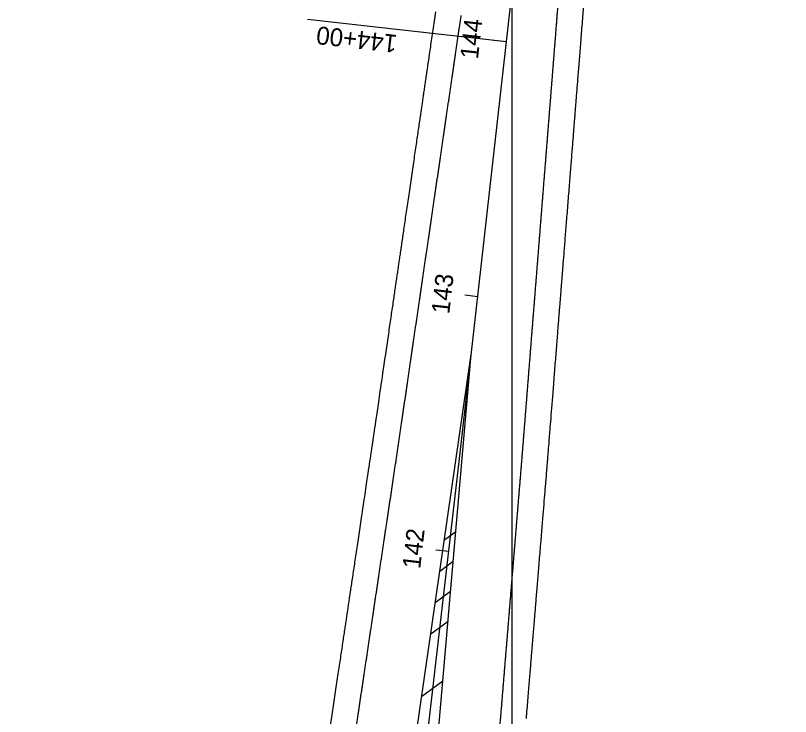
# Model space of a CAD drawing. Extents: x 2318076 to 2324211, y 613525 to 630327.
# Drawn here: x 2320476.3 to 2320778.2, y 628702.1 to 628975.4 of the extents above; entities that cross this region are included whole.
import ezdxf

# ---------------------------------------------------------------- set-up
doc = ezdxf.new("R2010")
doc.units = 0
for name, color, linetype in [('GE_P_CL_50', 7, 'Continuous'), ('PM_P_CL_Double_Solid', 7, 'Continuous'), ('PM_P_Transverse_Line', 7, 'Continuous'), ('PV_P_EOP', 7, 'Continuous'), ('PV_P_Shoulder', 7, 'Continuous'), ('SC_Scratch3', 7, 'Continuous')]:
    doc.layers.add(name, color=color, linetype=linetype)

msp = doc.modelspace()

# ---------------------------------------------------------------- linework, layer by layer
at = {"layer": 'GE_P_CL_50'}
for p, q in [((2320667.58, 628965.13), (2320590.07, 628973.86)), ((2320667.58, 628965.13), (2320662.61, 628965.69)), ((2320656.38, 628865.76), (2320651.41, 628866.32)), ((2320645.08, 628766.4), (2320640.11, 628766.97))]:
    msp.add_line(p, q, dxfattribs=at)
msp.add_lwpolyline([(2320476.3, 627307.7), (2320485.22, 627375.57), (2320502.11, 627520.92), (2320519.22, 627676.47), (2320531.82, 627783.89), (2320546.8, 627927.12), (2320554.45, 627991.34), (2320572.51, 628138.41), (2320649.52, 628804.84), (2320678.77, 629064.5), (2320690.76, 629163.78), (2320713.75, 629362.45), (2320725.26, 629461.78), (2320736.97, 629561.09), (2320748.4, 629660.43), (2320759.09, 629759.86), (2320769.62, 629859.3), (2320777.51, 629931.12), (2320778.25, 629937.84)], dxfattribs=at)
at = {"layer": 'PM_P_CL_Double_Solid'}
for p in [(2320623.21, 628631.42), (2320635.3, 628629.45)]:
    msp.add_line(p, (2320653.84, 628843.21), dxfattribs=at)
at = {"layer": 'PM_P_Transverse_Line'}
for p, q in [((2320647.85, 628774.12), (2320643.47, 628770.85)), ((2320646.84, 628762.47), (2320641.6, 628758.56)), ((2320645.83, 628750.83), (2320639.83, 628746.35)), ((2320644.82, 628739.18), (2320638.07, 628734.13)), ((2320642.8, 628715.89), (2320634.53, 628709.71))]:
    msp.add_line(p, q, dxfattribs=at)
at = {"layer": 'PV_P_EOP'}
for points in [[(2320687.04, 628971.2), (2320687.12, 628972.11), (2320687.19, 628973.02), (2320687.26, 628973.93), (2320687.33, 628974.84), (2320687.4, 628975.75), (2320687.48, 628976.66), (2320687.55, 628977.57), (2320687.62, 628978.48), (2320687.69, 628979.38), (2320687.77, 628980.29), (2320687.84, 628981.2), (2320687.91, 628982.11), (2320687.98, 628983.02), (2320688.05, 628983.93), (2320688.13, 628984.84), (2320688.2, 628985.75), (2320688.27, 628986.66), (2320688.34, 628987.57), (2320688.42, 628988.47), (2320688.49, 628989.38), (2320688.56, 628990.29), (2320688.63, 628991.2), (2320688.7, 628992.11), (2320688.78, 628993.02), (2320688.85, 628993.93), (2320688.92, 628994.84), (2320688.99, 628995.75), (2320689.07, 628996.66), (2320689.14, 628997.57), (2320689.21, 628998.47), (2320689.28, 628999.38), (2320689.35, 629000.29), (2320689.43, 629001.2), (2320689.5, 629002.11), (2320689.57, 629003.02), (2320689.64, 629003.93), (2320689.71, 629004.84), (2320689.79, 629005.75), (2320689.86, 629006.66), (2320689.93, 629007.56), (2320690, 629008.47), (2320690.08, 629009.38), (2320690.15, 629010.29), (2320690.22, 629011.2), (2320690.29, 629012.11), (2320690.36, 629013.02), (2320690.44, 629013.93), (2320690.51, 629014.84), (2320690.58, 629015.75), (2320690.65, 629016.65), (2320690.73, 629017.56), (2320690.8, 629018.47), (2320690.87, 629019.38), (2320690.94, 629020.29), (2320691.01, 629021.2), (2320691.09, 629022.11), (2320691.16, 629023.02), (2320691.23, 629023.93), (2320691.3, 629024.84), (2320691.37, 629025.75), (2320691.45, 629026.65), (2320691.52, 629027.56), (2320691.59, 629028.47), (2320691.66, 629029.38), (2320691.74, 629030.29), (2320691.81, 629031.2), (2320691.88, 629032.11), (2320691.95, 629033.02), (2320692.02, 629033.93), (2320692.1, 629034.84), (2320692.17, 629035.74), (2320692.24, 629036.65), (2320692.31, 629037.56), (2320692.39, 629038.47)], [(2320640.19, 628908.61), (2320640.32, 628909.51), (2320640.45, 628910.41), (2320640.58, 628911.32), (2320640.72, 628912.22), (2320640.85, 628913.12), (2320640.98, 628914.02), (2320641.11, 628914.93), (2320641.24, 628915.83), (2320641.37, 628916.73), (2320641.51, 628917.63), (2320641.64, 628918.54), (2320641.77, 628919.44), (2320641.9, 628920.34), (2320642.03, 628921.24), (2320642.17, 628922.14), (2320642.3, 628923.05), (2320642.43, 628923.95), (2320642.56, 628924.85), (2320642.69, 628925.75), (2320642.82, 628926.66), (2320642.96, 628927.56), (2320643.09, 628928.46), (2320643.22, 628929.36), (2320643.35, 628930.27), (2320643.48, 628931.17), (2320643.62, 628932.07), (2320643.75, 628932.97), (2320643.88, 628933.87), (2320644.01, 628934.78), (2320644.14, 628935.68), (2320644.28, 628936.58), (2320644.41, 628937.48), (2320644.54, 628938.39), (2320644.67, 628939.29), (2320644.8, 628940.19), (2320644.93, 628941.09), (2320645.07, 628942), (2320645.2, 628942.9), (2320645.33, 628943.8), (2320645.46, 628944.7), (2320645.59, 628945.6), (2320645.73, 628946.51), (2320645.86, 628947.41), (2320645.99, 628948.31), (2320646.12, 628949.21), (2320646.25, 628950.12), (2320646.39, 628951.02), (2320646.52, 628951.92), (2320646.65, 628952.82), (2320646.78, 628953.73), (2320646.91, 628954.63), (2320647.04, 628955.53), (2320647.18, 628956.43), (2320647.31, 628957.34), (2320647.44, 628958.24), (2320647.57, 628959.14), (2320647.7, 628960.04), (2320647.84, 628960.94), (2320647.97, 628961.85), (2320648.1, 628962.75), (2320648.23, 628963.65), (2320648.36, 628964.55), (2320648.49, 628965.46), (2320648.63, 628966.36), (2320648.76, 628967.26), (2320648.89, 628968.16), (2320649.02, 628969.07), (2320649.15, 628969.97), (2320649.29, 628970.87), (2320649.42, 628971.77), (2320649.55, 628972.67), (2320649.68, 628973.58), (2320649.81, 628974.48), (2320649.95, 628975.38)], [(2320681.7, 628903.93), (2320681.78, 628904.84), (2320681.85, 628905.75), (2320681.92, 628906.66), (2320681.99, 628907.57), (2320682.06, 628908.48), (2320682.14, 628909.39), (2320682.21, 628910.3), (2320682.28, 628911.21), (2320682.35, 628912.11), (2320682.42, 628913.02), (2320682.5, 628913.93), (2320682.57, 628914.84), (2320682.64, 628915.75), (2320682.71, 628916.66), (2320682.79, 628917.57), (2320682.86, 628918.48), (2320682.93, 628919.39), (2320683, 628920.3), (2320683.07, 628921.21), (2320683.15, 628922.11), (2320683.22, 628923.02), (2320683.29, 628923.93), (2320683.36, 628924.84), (2320683.44, 628925.75), (2320683.51, 628926.66), (2320683.58, 628927.57), (2320683.65, 628928.48), (2320683.72, 628929.39), (2320683.8, 628930.3), (2320683.87, 628931.2), (2320683.94, 628932.11), (2320684.01, 628933.02), (2320684.08, 628933.93), (2320684.16, 628934.84), (2320684.23, 628935.75), (2320684.3, 628936.66), (2320684.37, 628937.57), (2320684.45, 628938.48), (2320684.52, 628939.39), (2320684.59, 628940.3), (2320684.66, 628941.2), (2320684.73, 628942.11), (2320684.81, 628943.02), (2320684.88, 628943.93), (2320684.95, 628944.84), (2320685.02, 628945.75), (2320685.1, 628946.66), (2320685.17, 628947.57), (2320685.24, 628948.48), (2320685.31, 628949.39), (2320685.38, 628950.29), (2320685.46, 628951.2), (2320685.53, 628952.11), (2320685.6, 628953.02), (2320685.67, 628953.93), (2320685.74, 628954.84), (2320685.82, 628955.75), (2320685.89, 628956.66), (2320685.96, 628957.57), (2320686.03, 628958.48), (2320686.11, 628959.39), (2320686.18, 628960.29), (2320686.25, 628961.2), (2320686.32, 628962.11), (2320686.39, 628963.02), (2320686.47, 628963.93), (2320686.54, 628964.84), (2320686.61, 628965.75), (2320686.68, 628966.66), (2320686.76, 628967.57), (2320686.83, 628968.48), (2320686.9, 628969.38), (2320686.97, 628970.29), (2320687.04, 628971.2)], [(2320630.43, 628841.84), (2320630.56, 628842.74), (2320630.69, 628843.64), (2320630.83, 628844.54), (2320630.96, 628845.45), (2320631.09, 628846.35), (2320631.22, 628847.25), (2320631.35, 628848.15), (2320631.49, 628849.06), (2320631.62, 628849.96), (2320631.75, 628850.86), (2320631.88, 628851.76), (2320632.01, 628852.67), (2320632.14, 628853.57), (2320632.28, 628854.47), (2320632.41, 628855.37), (2320632.54, 628856.28), (2320632.67, 628857.18), (2320632.8, 628858.08), (2320632.94, 628858.98), (2320633.07, 628859.88), (2320633.2, 628860.79), (2320633.33, 628861.69), (2320633.46, 628862.59), (2320633.59, 628863.49), (2320633.73, 628864.4), (2320633.86, 628865.3), (2320633.99, 628866.2), (2320634.12, 628867.1), (2320634.25, 628868.01), (2320634.39, 628868.91), (2320634.52, 628869.81), (2320634.65, 628870.71), (2320634.78, 628871.61), (2320634.91, 628872.52), (2320635.05, 628873.42), (2320635.18, 628874.32), (2320635.31, 628875.22), (2320635.44, 628876.13), (2320635.57, 628877.03), (2320635.7, 628877.93), (2320635.84, 628878.83), (2320635.97, 628879.74), (2320636.1, 628880.64), (2320636.23, 628881.54), (2320636.36, 628882.44), (2320636.5, 628883.34), (2320636.63, 628884.25), (2320636.76, 628885.15), (2320636.89, 628886.05), (2320637.02, 628886.95), (2320637.16, 628887.86), (2320637.29, 628888.76), (2320637.42, 628889.66), (2320637.55, 628890.56), (2320637.68, 628891.47), (2320637.81, 628892.37), (2320637.95, 628893.27), (2320638.08, 628894.17), (2320638.21, 628895.07), (2320638.34, 628895.98), (2320638.47, 628896.88), (2320638.61, 628897.78), (2320638.74, 628898.68), (2320638.87, 628899.59), (2320639, 628900.49), (2320639.13, 628901.39), (2320639.26, 628902.29), (2320639.4, 628903.2), (2320639.53, 628904.1), (2320639.66, 628905), (2320639.79, 628905.9), (2320639.92, 628906.81), (2320640.06, 628907.71), (2320640.19, 628908.61)], [(2320676.36, 628836.66), (2320676.43, 628837.57), (2320676.51, 628838.48), (2320676.58, 628839.39), (2320676.65, 628840.3), (2320676.72, 628841.21), (2320676.8, 628842.12), (2320676.87, 628843.03), (2320676.94, 628843.94), (2320677.01, 628844.85), (2320677.08, 628845.75), (2320677.16, 628846.66), (2320677.23, 628847.57), (2320677.3, 628848.48), (2320677.37, 628849.39), (2320677.44, 628850.3), (2320677.52, 628851.21), (2320677.59, 628852.12), (2320677.66, 628853.03), (2320677.73, 628853.94), (2320677.81, 628854.84), (2320677.88, 628855.75), (2320677.95, 628856.66), (2320678.02, 628857.57), (2320678.09, 628858.48), (2320678.17, 628859.39), (2320678.24, 628860.3), (2320678.31, 628861.21), (2320678.38, 628862.12), (2320678.46, 628863.03), (2320678.53, 628863.94), (2320678.6, 628864.84), (2320678.67, 628865.75), (2320678.74, 628866.66), (2320678.82, 628867.57), (2320678.89, 628868.48), (2320678.96, 628869.39), (2320679.03, 628870.3), (2320679.1, 628871.21), (2320679.18, 628872.12), (2320679.25, 628873.03), (2320679.32, 628873.93), (2320679.39, 628874.84), (2320679.47, 628875.75), (2320679.54, 628876.66), (2320679.61, 628877.57), (2320679.68, 628878.48), (2320679.75, 628879.39), (2320679.83, 628880.3), (2320679.9, 628881.21), (2320679.97, 628882.12), (2320680.04, 628883.03), (2320680.12, 628883.93), (2320680.19, 628884.84), (2320680.26, 628885.75), (2320680.33, 628886.66), (2320680.4, 628887.57), (2320680.48, 628888.48), (2320680.55, 628889.39), (2320680.62, 628890.3), (2320680.69, 628891.21), (2320680.76, 628892.12), (2320680.84, 628893.02), (2320680.91, 628893.93), (2320680.98, 628894.84), (2320681.05, 628895.75), (2320681.13, 628896.66), (2320681.2, 628897.57), (2320681.27, 628898.48), (2320681.34, 628899.39), (2320681.41, 628900.3), (2320681.49, 628901.21), (2320681.56, 628902.12), (2320681.63, 628903.02), (2320681.7, 628903.93)], [(2320620.59, 628775.15), (2320620.72, 628776.05), (2320620.86, 628776.95), (2320620.99, 628777.85), (2320621.12, 628778.76), (2320621.26, 628779.66), (2320621.39, 628780.56), (2320621.53, 628781.46), (2320621.66, 628782.36), (2320621.8, 628783.27), (2320621.93, 628784.17), (2320622.07, 628785.07), (2320622.2, 628785.97), (2320622.34, 628786.87), (2320622.47, 628787.78), (2320622.6, 628788.68), (2320622.74, 628789.58), (2320622.87, 628790.48), (2320623.01, 628791.38), (2320623.14, 628792.29), (2320623.28, 628793.19), (2320623.41, 628794.09), (2320623.55, 628794.99), (2320623.68, 628795.89), (2320623.81, 628796.8), (2320623.95, 628797.7), (2320624.08, 628798.6), (2320624.22, 628799.5), (2320624.35, 628800.4), (2320624.49, 628801.31), (2320624.62, 628802.21), (2320624.76, 628803.11), (2320624.89, 628804.01), (2320625.02, 628804.91), (2320625.16, 628805.82), (2320625.29, 628806.72), (2320625.43, 628807.62), (2320625.55, 628808.45), (2320625.68, 628809.35), (2320625.82, 628810.26), (2320625.95, 628811.16), (2320626.08, 628812.06), (2320626.21, 628812.96), (2320626.34, 628813.87), (2320626.47, 628814.77), (2320626.61, 628815.67), (2320626.74, 628816.57), (2320626.87, 628817.48), (2320627, 628818.38), (2320627.13, 628819.28), (2320627.27, 628820.18), (2320627.4, 628821.08), (2320627.53, 628821.99), (2320627.66, 628822.89), (2320627.79, 628823.79), (2320627.92, 628824.69), (2320628.06, 628825.6), (2320628.19, 628826.5), (2320628.32, 628827.4), (2320628.45, 628828.3), (2320628.58, 628829.21), (2320628.72, 628830.11), (2320628.85, 628831.01), (2320628.98, 628831.91), (2320629.11, 628832.81), (2320629.24, 628833.72), (2320629.38, 628834.62), (2320629.51, 628835.52), (2320629.64, 628836.42), (2320629.77, 628837.33), (2320629.9, 628838.23), (2320630.03, 628839.13), (2320630.17, 628840.03), (2320630.3, 628840.94), (2320630.43, 628841.84)], [(2320670.92, 628769.33), (2320670.99, 628770.24), (2320671.07, 628771.15), (2320671.14, 628772.06), (2320671.22, 628772.97), (2320671.29, 628773.88), (2320671.37, 628774.79), (2320671.44, 628775.69), (2320671.52, 628776.6), (2320671.59, 628777.51), (2320671.67, 628778.42), (2320671.74, 628779.33), (2320671.82, 628780.24), (2320671.89, 628781.15), (2320671.97, 628782.06), (2320672.04, 628782.97), (2320672.12, 628783.87), (2320672.19, 628784.78), (2320672.27, 628785.69), (2320672.34, 628786.6), (2320672.41, 628787.51), (2320672.49, 628788.42), (2320672.56, 628789.33), (2320672.64, 628790.24), (2320672.71, 628791.14), (2320672.79, 628792.05), (2320672.86, 628792.96), (2320672.94, 628793.87), (2320673.01, 628794.78), (2320673.09, 628795.69), (2320673.16, 628796.6), (2320673.24, 628797.51), (2320673.31, 628798.42), (2320673.39, 628799.32), (2320673.46, 628800.23), (2320673.54, 628801.14), (2320673.61, 628802.05), (2320673.69, 628803.03), (2320673.76, 628803.94), (2320673.84, 628804.85), (2320673.91, 628805.76), (2320673.98, 628806.67), (2320674.05, 628807.57), (2320674.12, 628808.48), (2320674.2, 628809.39), (2320674.27, 628810.3), (2320674.34, 628811.21), (2320674.41, 628812.12), (2320674.49, 628813.03), (2320674.56, 628813.94), (2320674.63, 628814.85), (2320674.7, 628815.76), (2320674.77, 628816.67), (2320674.85, 628817.57), (2320674.92, 628818.48), (2320674.99, 628819.39), (2320675.06, 628820.3), (2320675.13, 628821.21), (2320675.21, 628822.12), (2320675.28, 628823.03), (2320675.35, 628823.94), (2320675.42, 628824.85), (2320675.5, 628825.76), (2320675.57, 628826.66), (2320675.64, 628827.57), (2320675.71, 628828.48), (2320675.78, 628829.39), (2320675.86, 628830.3), (2320675.93, 628831.21), (2320676, 628832.12), (2320676.07, 628833.03), (2320676.15, 628833.94), (2320676.22, 628834.85), (2320676.29, 628835.75), (2320676.36, 628836.66)], [(2320610.64, 628708.41), (2320610.77, 628709.31), (2320610.91, 628710.21), (2320611.04, 628711.11), (2320611.18, 628712.01), (2320611.31, 628712.92), (2320611.44, 628713.82), (2320611.58, 628714.72), (2320611.71, 628715.62), (2320611.85, 628716.52), (2320611.98, 628717.42), (2320612.12, 628718.33), (2320612.25, 628719.23), (2320612.39, 628720.13), (2320612.52, 628721.03), (2320612.65, 628721.93), (2320612.79, 628722.84), (2320612.92, 628723.74), (2320613.06, 628724.64), (2320613.19, 628725.54), (2320613.33, 628726.44), (2320613.46, 628727.35), (2320613.6, 628728.25), (2320613.73, 628729.15), (2320613.86, 628730.05), (2320614, 628730.95), (2320614.13, 628731.86), (2320614.27, 628732.76), (2320614.4, 628733.66), (2320614.54, 628734.56), (2320614.67, 628735.46), (2320614.81, 628736.37), (2320614.94, 628737.27), (2320615.07, 628738.17), (2320615.21, 628739.07), (2320615.34, 628739.97), (2320615.48, 628740.88), (2320615.61, 628741.78), (2320615.75, 628742.68), (2320615.88, 628743.58), (2320616.02, 628744.48), (2320616.15, 628745.39), (2320616.28, 628746.29), (2320616.42, 628747.19), (2320616.55, 628748.09), (2320616.69, 628748.99), (2320616.82, 628749.89), (2320616.96, 628750.8), (2320617.09, 628751.7), (2320617.23, 628752.6), (2320617.36, 628753.5), (2320617.49, 628754.4), (2320617.63, 628755.31), (2320617.76, 628756.21), (2320617.9, 628757.11), (2320618.03, 628758.01), (2320618.17, 628758.91), (2320618.3, 628759.82), (2320618.44, 628760.72), (2320618.57, 628761.62), (2320618.7, 628762.52), (2320618.84, 628763.42), (2320618.97, 628764.33), (2320619.11, 628765.23), (2320619.24, 628766.13), (2320619.38, 628767.03), (2320619.51, 628767.93), (2320619.65, 628768.84), (2320619.78, 628769.74), (2320619.91, 628770.64), (2320620.05, 628771.54), (2320620.18, 628772.44), (2320620.32, 628773.35), (2320620.45, 628774.25), (2320620.59, 628775.15)], [(2320665.38, 628702.08), (2320665.46, 628702.99), (2320665.53, 628703.9), (2320665.61, 628704.81), (2320665.68, 628705.71), (2320665.76, 628706.62), (2320665.83, 628707.53), (2320665.91, 628708.44), (2320665.98, 628709.35), (2320666.06, 628710.26), (2320666.13, 628711.17), (2320666.21, 628712.08), (2320666.28, 628712.99), (2320666.36, 628713.89), (2320666.43, 628714.8), (2320666.51, 628715.71), (2320666.58, 628716.62), (2320666.66, 628717.53), (2320666.73, 628718.44), (2320666.81, 628719.35), (2320666.88, 628720.26), (2320666.95, 628721.16), (2320667.03, 628722.07), (2320667.1, 628722.98), (2320667.18, 628723.89), (2320667.25, 628724.8), (2320667.33, 628725.71), (2320667.4, 628726.62), (2320667.48, 628727.53), (2320667.55, 628728.44), (2320667.63, 628729.34), (2320667.7, 628730.25), (2320667.78, 628731.16), (2320667.85, 628732.07), (2320667.93, 628732.98), (2320668, 628733.89), (2320668.08, 628734.8), (2320668.15, 628735.71), (2320668.23, 628736.61), (2320668.3, 628737.52), (2320668.38, 628738.43), (2320668.45, 628739.34), (2320668.53, 628740.25), (2320668.6, 628741.16), (2320668.68, 628742.07), (2320668.75, 628742.98), (2320668.82, 628743.89), (2320668.9, 628744.79), (2320668.97, 628745.7), (2320669.05, 628746.61), (2320669.12, 628747.52), (2320669.2, 628748.43), (2320669.27, 628749.34), (2320669.35, 628750.25), (2320669.42, 628751.16), (2320669.5, 628752.07), (2320669.57, 628752.97), (2320669.65, 628753.88), (2320669.72, 628754.79), (2320669.8, 628755.7), (2320669.87, 628756.61), (2320669.95, 628757.52), (2320670.02, 628758.43), (2320670.1, 628759.34), (2320670.17, 628760.24), (2320670.25, 628761.15), (2320670.32, 628762.06), (2320670.4, 628762.97), (2320670.47, 628763.88), (2320670.54, 628764.79), (2320670.62, 628765.7), (2320670.69, 628766.61), (2320670.77, 628767.52), (2320670.84, 628768.42), (2320670.92, 628769.33)], [(2320600.69, 628641.66), (2320600.82, 628642.56), (2320600.96, 628643.47), (2320601.09, 628644.37), (2320601.23, 628645.27), (2320601.36, 628646.17), (2320601.49, 628647.07), (2320601.63, 628647.98), (2320601.76, 628648.88), (2320601.9, 628649.78), (2320602.03, 628650.68), (2320602.17, 628651.58), (2320602.3, 628652.49), (2320602.44, 628653.39), (2320602.57, 628654.29), (2320602.7, 628655.19), (2320602.84, 628656.09), (2320602.97, 628657), (2320603.11, 628657.9), (2320603.24, 628658.8), (2320603.38, 628659.7), (2320603.51, 628660.6), (2320603.65, 628661.5), (2320603.78, 628662.41), (2320603.91, 628663.31), (2320604.05, 628664.21), (2320604.18, 628665.11), (2320604.32, 628666.01), (2320604.45, 628666.92), (2320604.59, 628667.82), (2320604.72, 628668.72), (2320604.86, 628669.62), (2320604.99, 628670.52), (2320605.12, 628671.43), (2320605.26, 628672.33), (2320605.39, 628673.23), (2320605.53, 628674.13), (2320605.66, 628675.03), (2320605.8, 628675.94), (2320605.93, 628676.84), (2320606.07, 628677.74), (2320606.2, 628678.64), (2320606.33, 628679.54), (2320606.47, 628680.45), (2320606.6, 628681.35), (2320606.74, 628682.25), (2320606.87, 628683.15), (2320607.01, 628684.05), (2320607.14, 628684.96), (2320607.28, 628685.86), (2320607.41, 628686.76), (2320607.55, 628687.66), (2320607.68, 628688.56), (2320607.81, 628689.46), (2320607.95, 628690.37), (2320608.08, 628691.27), (2320608.22, 628692.17), (2320608.35, 628693.07), (2320608.49, 628693.97), (2320608.62, 628694.88), (2320608.76, 628695.78), (2320608.89, 628696.68), (2320609.02, 628697.58), (2320609.16, 628698.48), (2320609.29, 628699.39), (2320609.43, 628700.29), (2320609.56, 628701.19), (2320609.7, 628702.09), (2320609.83, 628702.99), (2320609.97, 628703.9), (2320610.1, 628704.8), (2320610.23, 628705.7), (2320610.37, 628706.6), (2320610.5, 628707.5), (2320610.64, 628708.41)], [(2320659.85, 628634.83), (2320659.92, 628635.73), (2320660, 628636.64), (2320660.07, 628637.55), (2320660.15, 628638.46), (2320660.22, 628639.37), (2320660.3, 628640.28), (2320660.37, 628641.19), (2320660.45, 628642.1), (2320660.52, 628643.01), (2320660.6, 628643.91), (2320660.67, 628644.82), (2320660.75, 628645.73), (2320660.82, 628646.64), (2320660.9, 628647.55), (2320660.97, 628648.46), (2320661.05, 628649.37), (2320661.12, 628650.28), (2320661.2, 628651.18), (2320661.27, 628652.09), (2320661.35, 628653), (2320661.42, 628653.91), (2320661.5, 628654.82), (2320661.57, 628655.73), (2320661.64, 628656.64), (2320661.72, 628657.55), (2320661.79, 628658.46), (2320661.87, 628659.36), (2320661.94, 628660.27), (2320662.02, 628661.18), (2320662.09, 628662.09), (2320662.17, 628663), (2320662.24, 628663.91), (2320662.32, 628664.82), (2320662.39, 628665.73), (2320662.47, 628666.63), (2320662.54, 628667.54), (2320662.62, 628668.45), (2320662.69, 628669.36), (2320662.77, 628670.27), (2320662.84, 628671.18), (2320662.92, 628672.09), (2320662.99, 628673), (2320663.07, 628673.91), (2320663.14, 628674.81), (2320663.22, 628675.72), (2320663.29, 628676.63), (2320663.36, 628677.54), (2320663.44, 628678.45), (2320663.51, 628679.36), (2320663.59, 628680.27), (2320663.66, 628681.18), (2320663.74, 628682.08), (2320663.81, 628682.99), (2320663.89, 628683.9), (2320663.96, 628684.81), (2320664.04, 628685.72), (2320664.11, 628686.63), (2320664.19, 628687.54), (2320664.26, 628688.45), (2320664.34, 628689.36), (2320664.41, 628690.26), (2320664.49, 628691.17), (2320664.56, 628692.08), (2320664.64, 628692.99), (2320664.71, 628693.9), (2320664.79, 628694.81), (2320664.86, 628695.72), (2320664.94, 628696.63), (2320665.01, 628697.54), (2320665.09, 628698.44), (2320665.16, 628699.35), (2320665.23, 628700.26), (2320665.31, 628701.17), (2320665.38, 628702.08)]]:
    msp.add_spline(points, degree=3, dxfattribs=at)
at = {"layer": 'PV_P_Shoulder'}
for points, degree in [([(2320697.01, 628970.41), (2320698.79, 628992.83), (2320700.57, 629015.26), (2320702.35, 629037.68)], 2), ([(2320630.29, 628910.06), (2320633.55, 628932.31), (2320636.8, 628954.57), (2320640.05, 628976.83)], 2), ([(2320691.67, 628903.14), (2320693.45, 628925.56), (2320695.23, 628947.99), (2320697.01, 628970.41)], 2), ([(2320620.54, 628843.28), (2320623.79, 628865.54), (2320627.04, 628887.8), (2320630.29, 628910.06)], 2), ([(2320686.33, 628835.87), (2320688.11, 628858.3), (2320689.89, 628880.72), (2320691.67, 628903.14)], 2), ([(2320610.7, 628776.62), (2320611.52, 628782.18), (2320612.35, 628787.73), (2320613.59, 628796.07), (2320614.21, 628800.24), (2320614.94, 628805.11), (2320615.3, 628807.54), (2320615.46, 628808.58), (2320615.54, 628809.1), (2320615.56, 628809.28), (2320615.6, 628809.53), (2320615.62, 628809.65), (2320615.64, 628809.79), (2320615.65, 628809.85), (2320615.65, 628809.88), (2320615.66, 628809.89), (2320615.66, 628809.91), (2320617.28, 628821.04), (2320618.91, 628832.17), (2320620.54, 628843.28)], 3), ([(2320680.89, 628768.51), (2320681.35, 628774.13), (2320682.04, 628782.54), (2320682.84, 628792.36), (2320683.25, 628797.26), (2320683.45, 628799.71), (2320683.54, 628800.76), (2320683.58, 628801.29), (2320683.6, 628801.47), (2320683.63, 628801.83), (2320683.64, 628802.01), (2320683.66, 628802.21), (2320683.66, 628802.22), (2320683.66, 628802.25), (2320683.66, 628802.26), (2320683.66, 628802.29), (2320683.67, 628802.36), (2320683.68, 628802.51), (2320683.71, 628802.82), (2320683.75, 628803.43), (2320683.85, 628804.66), (2320684.05, 628807.11), (2320684.44, 628812.02), (2320685.22, 628821.84), (2320685.89, 628830.26), (2320686.33, 628835.87)], 3), ([(2320600.75, 628709.88), (2320604.06, 628732.13), (2320607.38, 628754.38), (2320610.7, 628776.62)], 2), ([(2320675.35, 628701.26), (2320677.2, 628723.68), (2320679.04, 628746.09), (2320680.89, 628768.51)], 2), ([(2320590.8, 628643.14), (2320594.11, 628665.38), (2320597.43, 628687.63), (2320600.75, 628709.88)], 2)]:
    msp.add_open_spline(points, degree=degree, dxfattribs=at)
at = {"layer": 'SC_Scratch3'}
msp.add_line((2320669.87, 614778.41), (2320669.87, 630327.22), dxfattribs=at)

# ---------------------------------------------------------------- texts
at = {"layer": 'GE_P_CL_50'}
for s, rotation, p in [('144+00', 173.5732, (2320625.27, 628967.72)), ('144', 83.5732, (2320656.47, 628958.15)), ('143', 83.5732, (2320645.28, 628858.77)), ('142', 83.4084, (2320633.95, 628759.43))]:
    msp.add_text(s, height=7, rotation=rotation, dxfattribs=at).set_placement(p)

doc.saveas('drawing.dxf')
